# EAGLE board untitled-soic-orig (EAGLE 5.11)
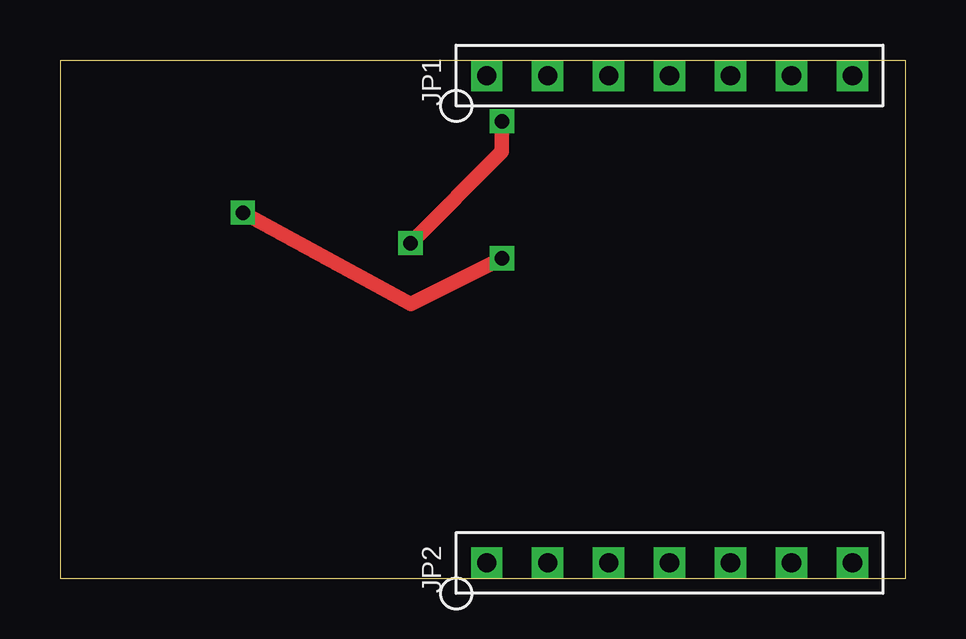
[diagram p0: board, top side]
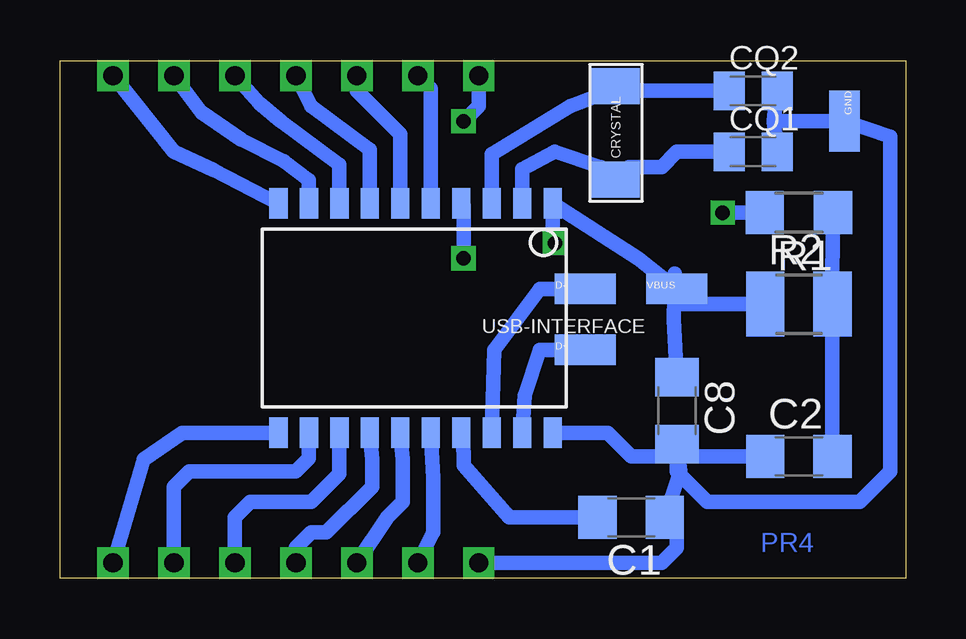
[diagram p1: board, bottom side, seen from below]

Size 35.23 x 21.58 mm. Coordinates in mm from the lower left corner, seen from the top.
Outline: 0,0 35.23,0 35.23,21.58 0,21.58 0,0
Copper layers (1*16): Top 0.035mm / dielectric 1.5mm / Bottom 0.035mm
Design rules "default": minimum track width 10mil, minimum drill 24mil, track to track 8mil, track to pad 8mil, pad to pad 8mil, via to via 8mil, smd to smd 8mil, copper to edge 40mil, drill to drill 8mil, minimum pad ring 10mil, minimum via ring 8mil, stop-mask expansion 4mil, vias tented up to drill 0mil, thermal gap 10mil

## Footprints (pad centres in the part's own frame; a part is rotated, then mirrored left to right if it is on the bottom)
C1206 = smd 1.6 x 1.8: 1 -1.4,0; 2 1.4,0
C0805K = smd 1.3 x 1.6: 1 -1,0; 2 1,0
CRYSTAL-5X3.2MM = smd 1.5 x 2: 1 -1.8,0; 2 2.1,0
WIREPAD-SMD-SMALL = smd 2.54 x 1.27: 1 0,0
SIL7 = drill 0.8 square: 1 0,6.35; 2 0,3.81; 3 0,1.27; 4 0,-1.27; 5 0,-3.81; 6 0,-6.35; 7 0,-8.89
R1206 = smd 1.6 x 1.803: 1 -1.422,0; 2 1.422,0
R1210 = smd 1.6 x 2.7: 1 -1.4,0; 2 1.4,0
SO20W = smd 0.762 x 1.27: 1 -5.62,-4.83; 2 -4.35,-4.83; 3 -3.08,-4.83; 4 -1.81,-4.83; 5 -0.54,-4.83; 6 0.73,-4.83; 7 2,-4.83; 8 3.27,-4.83; 9 4.54,-4.83; 10 5.81,-4.83; 11 5.81,4.73; 12 4.54,4.73; 13 3.27,4.73; 14 2,4.73; 15 0.73,4.73; 16 -0.54,4.73; 17 -1.81,4.73; 18 -3.08,4.73; 19 -4.35,4.73; 20 -5.62,4.73

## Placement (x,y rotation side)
C1  0.47uf  [C1206]  11.43,2.54 180 bottom
C2  0.1uf  [C1206]  4.45,5.08 0 bottom
C8  0.1uf  [C1206]  9.53,6.99 270 bottom
CQ1  22pf  [C0805K]  6.35,17.78 0 bottom
CQ2  22pf  [C0805K]  6.35,20.32 0 bottom
CRYSTAL  12mhz  [CRYSTAL-5X3.2MM]  12.06,18.41 90 bottom
D+  WIREPAD-SMD-SMALL-NAMED  [WIREPAD-SMD-SMALL]  13.34,9.53 0 bottom
D-  WIREPAD-SMD-SMALL-NAMED  [WIREPAD-SMD-SMALL]  13.34,12.06 0 bottom
GND  WIREPAD-SMD-SMALL-NAMED  [WIREPAD-SMD-SMALL]  2.54,19.05 270 bottom
JP1  [SIL7]  24.13,20.95 90 top
JP2  [SIL7]  24.13,0.64 90 top
R1  470  [R1206]  4.45,15.24 180 bottom
R2  10k  [R1210]  4.45,11.43 0 bottom
USB-INTERFACE  MCP2200-SOICW  [SO20W]  20.32,10.79 180 bottom
VBUS  WIREPAD-SMD-SMALL-NAMED  [WIREPAD-SMD-SMALL]  9.53,12.06 0 bottom

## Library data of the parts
C1 C2 C8 CQ1 CQ2 R1 R2 = resistor
CRYSTAL D+ D- GND JP1 JP2 USB-INTERFACE VBUS = trl

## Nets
GND: C1.1 C2.1 C8.2 CQ1.2 CQ2.2 GND.1 JP2.1 USB-INTERFACE.20
N$1: R1.2 USB-INTERFACE.4
N$2: C2.2 R1.1 R2.2
N$4: D-.1 USB-INTERFACE.18
N$5: D+.1 USB-INTERFACE.19
N$7: JP1.7 USB-INTERFACE.10
N$8: JP1.6 USB-INTERFACE.9
N$11: JP1.5 USB-INTERFACE.8
N$12: JP1.4 USB-INTERFACE.7
N$13: JP1.3 USB-INTERFACE.6
N$14: JP1.2 USB-INTERFACE.5
N$15: CQ1.1 CRYSTAL.1 USB-INTERFACE.2
N$16: CQ2.1 CRYSTAL.2 USB-INTERFACE.3
N$21: JP2.7 USB-INTERFACE.11
N$22: JP2.6 USB-INTERFACE.12
N$23: JP2.5 USB-INTERFACE.13
N$24: JP2.4 USB-INTERFACE.14
N$25: JP2.3 USB-INTERFACE.15
N$26: JP2.2 USB-INTERFACE.16
N$28: C1.2 USB-INTERFACE.17
VBUS: C8.1 JP1.1 R2.1 USB-INTERFACE.1 VBUS.1

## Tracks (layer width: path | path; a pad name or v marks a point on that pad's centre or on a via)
GND
  Bottom 0.61: C8.2 9.39,4.45 C1.1 9.53,2.04 9.53,1.27 10.16,0.64 JP2.1 | C2.1 9.02,5.08 C8.2 | 9.53,5.08 9.53,4.45 8.26,3.17 1.91,3.17 0.64,4.45 0.64,18.41 GND.1 5.5,19.05 | 9.53,5.08 C8.2 | 5.5,19.05 CQ1.2 | 5.5,19.05 CQ2.2 | USB-INTERFACE.20 12.41,6.07 11.43,5.08 9.53,5.08
N$1  (via drill 0.6)
  Top 0.61: v7.62,15.24 14.61,11.43 v18.41,13.34
  Bottom 0.61: R1.2 v7.62,15.24 | v18.41,13.34 18.41,15.53 USB-INTERFACE.4
N$2
  Bottom 0.61: C2.2 3.04,11.41 R2.2 R1.1
N$4
  Bottom 0.61: USB-INTERFACE.18 17.14,9.53 15.24,12.06 D-.1
N$5
  Bottom 0.61: USB-INTERFACE.19 15.88,7.62 15.24,9.53 D+.1
N$7
  Bottom 0.61: USB-INTERFACE.10 28.83,17.02 30.48,17.78 JP1.7
N$8
  Bottom 0.61: USB-INTERFACE.9 24.86,16.61 25.91,17.4 27.69,18.29 29.34,19.43 JP1.6
N$11
  Bottom 0.61: USB-INTERFACE.8 23.59,17.24 26.04,19.05 26.92,19.81 JP1.5
N$12
  Bottom 0.61: USB-INTERFACE.7 22.32,17.88 24.77,19.68 JP1.4
N$13
  Bottom 0.61: USB-INTERFACE.6 21.05,18.51 22.86,20.32 JP1.3
N$14
  Bottom 0.61: USB-INTERFACE.5 19.78,20.41 JP1.2
N$15
  Bottom 0.61: CQ1.1 9.53,17.78 10.16,17.14 11.54,17.14 CRYSTAL.1 12.17,16.51 12.7,16.51 12.7,17.14 14.61,17.78 15.97,17.05 USB-INTERFACE.2
N$16
  Bottom 0.61: CQ2.1 11.87,20.32 CRYSTAL.2 12.26,20.32 13.97,19.68 17.24,17.68 USB-INTERFACE.3
N$21
  Bottom 0.61: USB-INTERFACE.11 30.13,6.07 31.75,4.95 JP2.7
N$22
  Bottom 0.61: USB-INTERFACE.12 24.86,4.99 25.4,4.45 29.84,4.45 30.48,3.81 JP2.6
N$23
  Bottom 0.61: USB-INTERFACE.13 23.59,4.35 24.77,3.17 27.3,3.17 27.94,2.54 JP2.5
N$24
  Bottom 0.61: JP2.4 25.4,1.27 24.77,1.91 24.13,1.91 22.23,3.81 22.23,4.95 USB-INTERFACE.14
N$25
  Bottom 0.61: JP2.3 21.59,2.54 20.95,3.17 20.95,4.95 USB-INTERFACE.15
N$26
  Bottom 0.61: JP2.2 19.68,1.91 19.68,4.19 USB-INTERFACE.16
N$28
  Bottom 0.61: C1.2 16.51,2.54 18.41,4.7 18.41,5.21 USB-INTERFACE.17
VBUS  (via drill 0.6)
  Top 0.61: v14.61,13.97 18.41,17.78 v18.41,19.05
  Bottom 0.61: 9.61,12.7 9.65,10.79 C8.1 | 9.61,12.7 VBUS.1 11.14,13.34 USB-INTERFACE.1 14.7,14.06 v14.61,13.97 | R2.1 9.61,11.43 9.61,12.7 | JP1.1 17.78,19.68 v18.41,19.05

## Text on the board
Bottom: PR4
